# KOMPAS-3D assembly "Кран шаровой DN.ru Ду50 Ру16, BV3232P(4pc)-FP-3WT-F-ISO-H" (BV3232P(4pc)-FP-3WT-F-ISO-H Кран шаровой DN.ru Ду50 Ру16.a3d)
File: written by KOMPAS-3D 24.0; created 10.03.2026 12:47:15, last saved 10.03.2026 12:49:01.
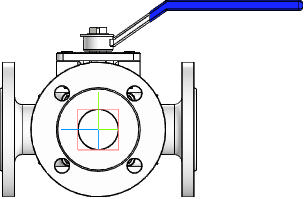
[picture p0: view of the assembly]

Document properties: Автор: R2D2; Полное имя файла: E:\Работа\Зайцев\BV3232P(4pc)-FP-3WT-F-ISO-H Кран шаровой DN.ru Ду15-100 Ру16\DN50\исходные материалы\BV3232P(4pc)-FP-3WT-F-ISO-H Кран шаровой DN.ru Ду50 Ру16.a3d

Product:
- Component [assembly]: Сборка1  | qty 1  | pos. 1  | Масса: 19.818804; Автор: R2D2; source file: dn50_3d_step.a3d
- Part/product: Кран шаровой DN.ru Ду50 Ру16  | designation BV3232P(4pc)-FP-3WT-F-ISO-H
    Масса: 17.95
    Раздел спецификации: Прочие изделия
    Примечание: D160-36351

Referenced files in E:\Работа\Зайцев\BV3232P(4pc)-FP-3WT-F-ISO-H Кран шаровой DN.ru Ду15-100 Ру16\DN50\исходные материалы\: dn50_3d_step.a3d
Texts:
  BV3232P(4pc)-FP-3WT-F-ISO-H
  Сборка1 Сборка1
  Ось Z.Начало координат
  Ось Y.Начало координат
